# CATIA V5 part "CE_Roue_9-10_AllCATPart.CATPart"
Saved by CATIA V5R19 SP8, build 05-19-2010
Part number: CE13_Roue_9-10_AllCATPart
Bounding box of the stored display mesh (mm): x -81.315 to -57.821, y 119.58 to 139.871, z 116.999 to 131.414
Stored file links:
  D:\Documents\1_Travail\1 - ac-limoges.fr\ac-limoges.fr\Emmanuel Maynard - STI2D_Turgot\2 -2I2D\1_SEQUENCE_ Tapis_de_course\3- Spécificités\Spé_ITEC\3-Pente\Tapis_TC520B_Pente\CE_Roue_9-10_AllCATPart.CATPart
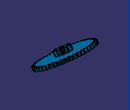
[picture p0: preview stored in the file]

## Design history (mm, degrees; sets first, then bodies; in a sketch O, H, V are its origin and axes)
AxisSystem1: origin (0, 0, 0), X (1, 0, 0), Y (0, 1, 0), Z (0, 0, 1)
Body1 (main body)
Body2 "Roue_10.1\\Corps principal"
  Solid1: solid without history
Body3 "Roue_9.1\\Corps principal"
  Solid2 "Solide.1": solid without history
